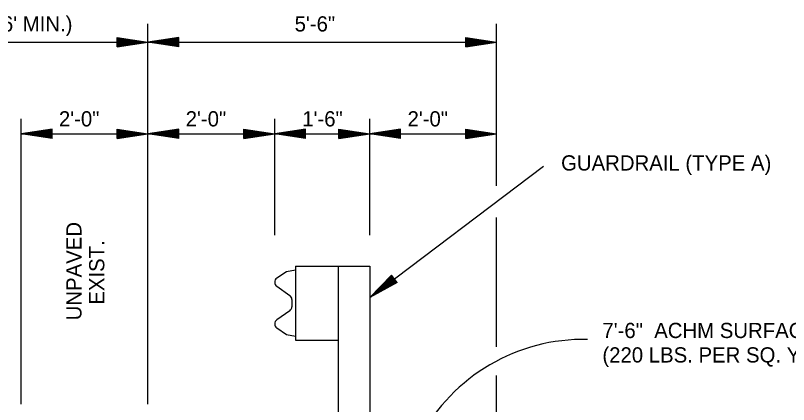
# Model space of a CAD drawing. Extents: x 1374136 to 1374281, y 380549 to 380948.
# Drawn here: x 1374151.8 to 1374182.29, y 380875.1 to 380890.45 of the extents above; entities that cross this region are included whole.
import ezdxf

# ---------------------------------------------------------------- set-up
doc = ezdxf.new("R2010")
doc.units = 0
doc.layers.add('Default', color=7, linetype='Continuous')

msp = doc.modelspace()

# ---------------------------------------------------------------- linework, layer by layer
at = {"layer": 'Default'}
for p, q in [((1374157.027, 380875.114), (1374157.027, 380890.113)), ((1374170.777, 380883.73), (1374170.777, 380890.113)), ((1374137.027, 380889.388), (1374157.027, 380889.388)), ((1374155.81, 380889.571), (1374157.027, 380889.388)), ((1374155.81, 380889.204), (1374155.81, 380889.571)), ((1374155.81, 380889.54), (1374156.823, 380889.388)), ((1374155.81, 380889.508), (1374156.614, 380889.388)), ((1374155.81, 380889.479), (1374156.41, 380889.388)), ((1374155.81, 380889.447), (1374156.206, 380889.389)), ((1374155.81, 380889.416), (1374156.002, 380889.389)), ((1374155.81, 380889.328), (1374156.206, 380889.389)), ((1374155.81, 380889.36), (1374156.002, 380889.389)), ((1374155.81, 380889.204), (1374157.027, 380889.388)), ((1374155.81, 380889.267), (1374156.614, 380889.388)), ((1374155.81, 380889.236), (1374156.823, 380889.388)), ((1374155.81, 380889.297), (1374156.41, 380889.388)), ((1374158.245, 380889.571), (1374157.027, 380889.388)), ((1374157.027, 380889.388), (1374170.777, 380889.388)), ((1374158.245, 380889.204), (1374157.027, 380889.388)), ((1374158.245, 380889.54), (1374157.232, 380889.388)), ((1374158.245, 380889.236), (1374157.232, 380889.388)), ((1374158.245, 380889.508), (1374157.441, 380889.388)), ((1374158.245, 380889.267), (1374157.441, 380889.388)), ((1374158.245, 380889.479), (1374157.645, 380889.388)), ((1374158.245, 380889.297), (1374157.645, 380889.388)), ((1374158.245, 380889.447), (1374157.849, 380889.389)), ((1374158.245, 380889.328), (1374157.849, 380889.389)), ((1374158.245, 380889.416), (1374158.053, 380889.389)), ((1374158.245, 380889.36), (1374158.053, 380889.389)), ((1374158.245, 380889.204), (1374158.245, 380889.571)), ((1374169.56, 380889.571), (1374170.777, 380889.388)), ((1374169.56, 380889.204), (1374169.56, 380889.571)), ((1374169.56, 380889.54), (1374170.573, 380889.388)), ((1374169.56, 380889.508), (1374170.364, 380889.388)), ((1374169.56, 380889.479), (1374170.16, 380889.388)), ((1374169.56, 380889.447), (1374169.956, 380889.389)), ((1374169.56, 380889.416), (1374169.752, 380889.389)), ((1374169.56, 380889.328), (1374169.956, 380889.389)), ((1374169.56, 380889.36), (1374169.752, 380889.389)), ((1374169.56, 380889.204), (1374170.777, 380889.388)), ((1374169.56, 380889.267), (1374170.364, 380889.388)), ((1374169.56, 380889.236), (1374170.573, 380889.388)), ((1374169.56, 380889.297), (1374170.16, 380889.388)), ((1374152.027, 380875.114), (1374152.027, 380886.369)), ((1374162.027, 380881.787), (1374162.027, 380886.369)), ((1374165.777, 380881.787), (1374165.777, 380886.369)), ((1374153.245, 380885.96), (1374152.027, 380885.777)), ((1374153.245, 380885.929), (1374152.232, 380885.777)), ((1374153.245, 380885.593), (1374153.245, 380885.96)), ((1374155.81, 380885.96), (1374157.027, 380885.777)), ((1374155.81, 380885.593), (1374155.81, 380885.96)), ((1374155.81, 380885.929), (1374156.823, 380885.777)), ((1374158.245, 380885.96), (1374157.027, 380885.777)), ((1374158.245, 380885.929), (1374157.232, 380885.777)), ((1374158.245, 380885.593), (1374158.245, 380885.96)), ((1374160.81, 380885.96), (1374162.027, 380885.777)), ((1374160.81, 380885.593), (1374160.81, 380885.96)), ((1374160.81, 380885.929), (1374161.823, 380885.777)), ((1374163.245, 380885.96), (1374162.027, 380885.777)), ((1374163.245, 380885.929), (1374162.232, 380885.777)), ((1374163.245, 380885.593), (1374163.245, 380885.96)), ((1374164.56, 380885.96), (1374165.777, 380885.777)), ((1374164.56, 380885.593), (1374164.56, 380885.96)), ((1374164.56, 380885.929), (1374165.573, 380885.777)), ((1374166.995, 380885.96), (1374165.777, 380885.777)), ((1374166.995, 380885.929), (1374165.982, 380885.777)), ((1374166.995, 380885.593), (1374166.995, 380885.96)), ((1374169.56, 380885.96), (1374170.777, 380885.777)), ((1374169.56, 380885.593), (1374169.56, 380885.96)), ((1374169.56, 380885.929), (1374170.573, 380885.777)), ((1374152.027, 380885.777), (1374157.027, 380885.777)), ((1374153.245, 380885.593), (1374152.027, 380885.777)), ((1374153.245, 380885.625), (1374152.232, 380885.777)), ((1374153.245, 380885.897), (1374152.441, 380885.777)), ((1374153.245, 380885.656), (1374152.441, 380885.777)), ((1374153.245, 380885.868), (1374152.645, 380885.777)), ((1374153.245, 380885.686), (1374152.645, 380885.777)), ((1374153.245, 380885.836), (1374152.849, 380885.778)), ((1374153.245, 380885.717), (1374152.849, 380885.778)), ((1374153.245, 380885.805), (1374153.053, 380885.778)), ((1374153.245, 380885.749), (1374153.053, 380885.778)), ((1374155.81, 380885.897), (1374156.614, 380885.777)), ((1374155.81, 380885.868), (1374156.41, 380885.777)), ((1374155.81, 380885.836), (1374156.206, 380885.778)), ((1374155.81, 380885.805), (1374156.002, 380885.778)), ((1374155.81, 380885.717), (1374156.206, 380885.778)), ((1374155.81, 380885.749), (1374156.002, 380885.778)), ((1374155.81, 380885.593), (1374157.027, 380885.777)), ((1374155.81, 380885.656), (1374156.614, 380885.777)), ((1374155.81, 380885.625), (1374156.823, 380885.777)), ((1374155.81, 380885.686), (1374156.41, 380885.777)), ((1374157.027, 380885.777), (1374162.027, 380885.777)), ((1374158.245, 380885.593), (1374157.027, 380885.777)), ((1374158.245, 380885.625), (1374157.232, 380885.777)), ((1374158.245, 380885.897), (1374157.441, 380885.777)), ((1374158.245, 380885.656), (1374157.441, 380885.777)), ((1374158.245, 380885.868), (1374157.645, 380885.777)), ((1374158.245, 380885.686), (1374157.645, 380885.777)), ((1374158.245, 380885.836), (1374157.849, 380885.778)), ((1374158.245, 380885.717), (1374157.849, 380885.778)), ((1374158.245, 380885.805), (1374158.053, 380885.778)), ((1374158.245, 380885.749), (1374158.053, 380885.778)), ((1374160.81, 380885.897), (1374161.614, 380885.777)), ((1374160.81, 380885.868), (1374161.41, 380885.777)), ((1374160.81, 380885.836), (1374161.206, 380885.778)), ((1374160.81, 380885.805), (1374161.002, 380885.778)), ((1374160.81, 380885.717), (1374161.206, 380885.778)), ((1374160.81, 380885.749), (1374161.002, 380885.778)), ((1374160.81, 380885.593), (1374162.027, 380885.777)), ((1374160.81, 380885.656), (1374161.614, 380885.777)), ((1374160.81, 380885.625), (1374161.823, 380885.777)), ((1374160.81, 380885.686), (1374161.41, 380885.777)), ((1374162.027, 380885.777), (1374165.777, 380885.777)), ((1374163.245, 380885.593), (1374162.027, 380885.777)), ((1374163.245, 380885.625), (1374162.232, 380885.777)), ((1374163.245, 380885.897), (1374162.441, 380885.777)), ((1374163.245, 380885.656), (1374162.441, 380885.777)), ((1374163.245, 380885.868), (1374162.645, 380885.777)), ((1374163.245, 380885.686), (1374162.645, 380885.777)), ((1374163.245, 380885.836), (1374162.849, 380885.778)), ((1374163.245, 380885.717), (1374162.849, 380885.778)), ((1374163.245, 380885.805), (1374163.053, 380885.778)), ((1374163.245, 380885.749), (1374163.053, 380885.778)), ((1374164.56, 380885.897), (1374165.364, 380885.777)), ((1374164.56, 380885.868), (1374165.16, 380885.777)), ((1374164.56, 380885.836), (1374164.956, 380885.778)), ((1374164.56, 380885.805), (1374164.752, 380885.778)), ((1374164.56, 380885.717), (1374164.956, 380885.778)), ((1374164.56, 380885.749), (1374164.752, 380885.778)), ((1374164.56, 380885.593), (1374165.777, 380885.777)), ((1374164.56, 380885.656), (1374165.364, 380885.777)), ((1374164.56, 380885.625), (1374165.573, 380885.777)), ((1374164.56, 380885.686), (1374165.16, 380885.777)), ((1374165.777, 380885.777), (1374170.777, 380885.777)), ((1374166.995, 380885.593), (1374165.777, 380885.777)), ((1374166.995, 380885.625), (1374165.982, 380885.777)), ((1374166.995, 380885.897), (1374166.191, 380885.777)), ((1374166.995, 380885.656), (1374166.191, 380885.777)), ((1374166.995, 380885.868), (1374166.395, 380885.777)), ((1374166.995, 380885.686), (1374166.395, 380885.777)), ((1374166.995, 380885.836), (1374166.599, 380885.778)), ((1374166.995, 380885.717), (1374166.599, 380885.778)), ((1374166.995, 380885.805), (1374166.803, 380885.778)), ((1374166.995, 380885.749), (1374166.803, 380885.778)), ((1374169.56, 380885.897), (1374170.364, 380885.777)), ((1374169.56, 380885.868), (1374170.16, 380885.777)), ((1374169.56, 380885.836), (1374169.956, 380885.778)), ((1374169.56, 380885.805), (1374169.752, 380885.778)), ((1374169.56, 380885.717), (1374169.956, 380885.778)), ((1374169.56, 380885.749), (1374169.752, 380885.778)), ((1374169.56, 380885.593), (1374170.777, 380885.777)), ((1374169.56, 380885.656), (1374170.364, 380885.777)), ((1374169.56, 380885.625), (1374170.573, 380885.777)), ((1374169.56, 380885.686), (1374170.16, 380885.777)), ((1374165.777, 380879.324), (1374172.623, 380884.498)), ((1374170.777, 380877.376), (1374170.777, 380882.476)), ((1374162.852, 380880.564), (1374165.777, 380880.564)), ((1374162.852, 380880.564), (1374162.852, 380877.639)), ((1374164.527, 380880.564), (1374164.527, 380865.616)), ((1374165.777, 380880.564), (1374165.777, 380865.616)), ((1374162.489, 380880.336), (1374162.113, 380880.084)), ((1374162.852, 380880.406), (1374162.489, 380880.336)), ((1374166.64, 380880.202), (1374165.777, 380879.324)), ((1374166.66, 380880.18), (1374165.939, 380879.445)), ((1374166.681, 380880.151), (1374166.112, 380879.577)), ((1374166.694, 380880.127), (1374166.272, 380879.697)), ((1374166.857, 380879.914), (1374166.64, 380880.202)), ((1374166.857, 380879.914), (1374165.777, 380879.324)), ((1374166.842, 380879.936), (1374165.939, 380879.445)), ((1374166.819, 380879.962), (1374166.112, 380879.577)), ((1374166.801, 380879.987), (1374166.272, 380879.697)), ((1374166.713, 380880.106), (1374166.432, 380879.82)), ((1374166.781, 380880.013), (1374166.432, 380879.82)), ((1374166.731, 380880.08), (1374166.596, 380879.944)), ((1374166.768, 380880.04), (1374166.596, 380879.944)), ((1374162.11, 380879.763), (1374162.622, 380879.405)), ((1374162.704, 380879.246), (1374162.704, 380879.102)), ((1374162.704, 380879.102), (1374162.704, 380878.958)), ((1374162.622, 380878.799), (1374162.11, 380878.44)), ((1374162.113, 380878.12), (1374162.489, 380877.868)), ((1374162.489, 380877.868), (1374162.852, 380877.797)), ((1374162.852, 380877.639), (1374164.527, 380877.639)), ((1374170.777, 380874.406), (1374170.777, 380876.243))]:
    msp.add_line(p, q, dxfattribs=at)
for centre, radius, start, end in [((1374162.222, 380879.923), 0.195, 124.158, 234.7471), ((1374162.509, 380879.246), 0.195, 360, 54.7471), ((1374162.509, 380878.958), 0.195, 305.2529, 0), ((1374162.222, 380878.281), 0.195, 125.2529, 235.842), ((1374174.22, 380870.331), 7.341, 88.8267, 151.8416)]:
    msp.add_arc(centre, radius, start, end, dxfattribs=at)

# ---------------------------------------------------------------- texts
for s, p in [("EXISTING SHOULDER (10' MAX., 6' MIN.)", (1374138.675, 380889.813)), ('5\'-6"', (1374162.813, 380889.813)), ('2\'-0"', (1374153.516, 380886.069)), ('2\'-0"', (1374158.516, 380886.069)), ('1\'-6"', (1374163.114, 380886.069)), ('2\'-0"', (1374167.266, 380886.069)), ('GUARDRAIL (TYPE A)', (1374173.323, 380884.33)), ('7\'-6"  ACHM SURFACE COURSE (1/2")', (1374174.953, 380877.723)), ('(220 LBS. PER SQ. YD.)', (1374174.953, 380876.759))]:
    msp.add_text(s, height=0.6, dxfattribs=at).set_placement(p)
for s, p in [('UNPAVED', (1374154.407, 380878.422)), ('EXIST.', (1374155.307, 380879.038))]:
    msp.add_text(s, height=0.6, rotation=90, dxfattribs=at).set_placement(p)

doc.saveas('drawing.dxf')
